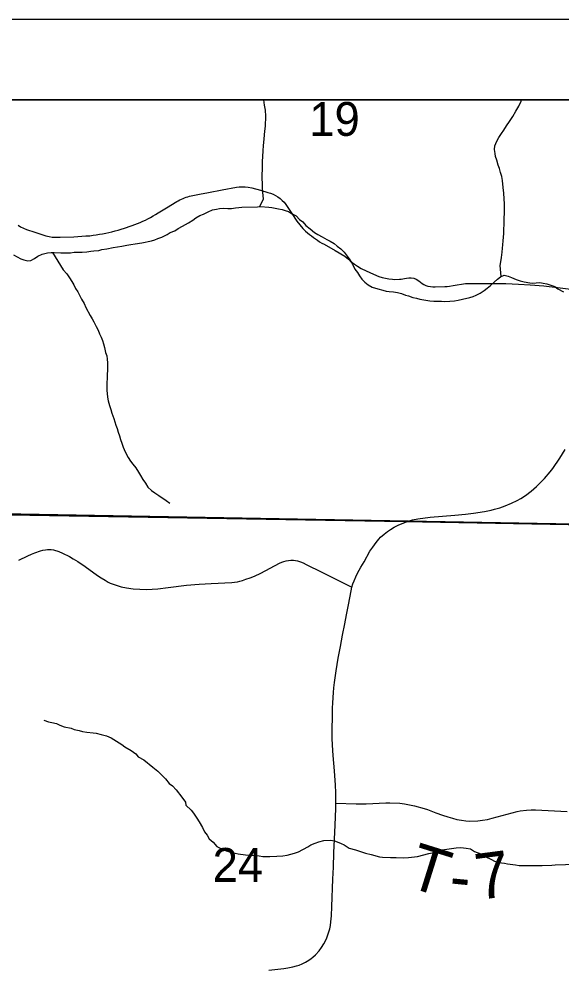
# Model space of a CAD drawing. Extents: x 0 to 34, y 0 to 22.
# Drawn here: x 29.074 to 29.746, y 19.826 to 21 of the extents above; entities that cross this region are included whole.
import ezdxf

# ---------------------------------------------------------------- set-up
doc = ezdxf.new("R2010")
doc.units = 0
for name, color, linetype in [('GM_X_Corporation', 7, 'Continuous'), ('GM_X_County_Road', 7, 'Continuous'), ('GM_X_Minor_River', 7, 'Continuous'), ('GM_X_Section_Text', 7, 'Continuous'), ('GM_X_Township_Road', 7, 'Continuous'), ('GM_X_Township_Road_Text', 7, 'Continuous'), ('SH_Data', 7, 'Continuous')]:
    doc.layers.add(name, color=color, linetype=linetype)

msp = doc.modelspace()

# ---------------------------------------------------------------- linework, layer by layer
at = {"layer": 'GM_X_Corporation'}
for points in [[(30.3167, 20.3649), (30.3167, 20.9), (27.1022, 20.9), (27.0898, 20.417), (27.1239, 20.4163), (27.2336, 20.4152), (27.5829, 20.4116), (27.6751, 20.4106), (29.5503, 20.3788)], [(29.9786, 20.9), (28.9521, 20.9), (28.9396, 20.3907), (29.9657, 20.3723)], [(29.9657, 20.3723), (29.946, 19.5413), (28.9198, 19.5578), (28.9396, 20.3907)]]:
    msp.add_lwpolyline(points, close=True, dxfattribs=at)
for points in [[(27.8031, 14.5091), (28.4032, 14.497), (28.7853, 14.4893), (29.1713, 14.4832), (29.2367, 14.4822), (30.3098, 14.464), (30.3167, 14.4639), (30.3167, 20.9), (27.1022, 20.9)], [(27.8031, 14.5091), (28.4032, 14.497), (28.7853, 14.4893), (29.1713, 14.4832), (29.2367, 14.4822), (30.3098, 14.464), (30.3167, 14.4639), (30.3167, 20.3649), (29.5503, 20.3788), (27.6751, 20.4106)]]:
    msp.add_lwpolyline(points, dxfattribs=at)
at = {"layer": 'GM_X_County_Road'}
for points in [[(29.5828, 20.3842), (29.6129, 20.3866), (29.6261, 20.3879), (29.6362, 20.3891), (29.6497, 20.3912), (29.6581, 20.3928), (29.6623, 20.3939), (29.6689, 20.3958), (29.6753, 20.3981), (29.683, 20.4013), (29.69, 20.4047), (29.6945, 20.4073), (29.7006, 20.4111), (29.7074, 20.4161), (29.7142, 20.422), (29.7206, 20.4285), (29.7239, 20.432), (29.7311, 20.4403), (29.7343, 20.4445), (29.7427, 20.457), (29.7494, 20.4679)], [(29.3833, 19.8242), (29.4016, 19.8262), (29.4065, 19.8269), (29.4127, 19.8282), (29.4172, 19.8293), (29.4208, 19.8304), (29.4243, 19.8318), (29.4286, 19.8339), (29.4326, 19.8363), (29.4356, 19.8385), (29.4374, 19.84), (29.4407, 19.843), (29.4452, 19.8479), (29.4482, 19.852), (29.4512, 19.8567), (29.4546, 19.863), (29.4566, 19.869), (29.4585, 19.8753), (29.4594, 19.8794), (29.46, 19.8837), (29.4605, 19.8912), (29.4612, 19.903), (29.4624, 19.9364), (29.463, 19.9514), (29.4637, 19.9692), (29.4644, 19.986), (29.4651, 20.0034), (29.466, 20.0238), (29.466, 20.0304), (29.4659, 20.0439), (29.4655, 20.0529), (29.4643, 20.0707), (29.4626, 20.0894), (29.4618, 20.1024), (29.4614, 20.1109), (29.4613, 20.1202), (29.4617, 20.139), (29.4619, 20.1482), (29.4623, 20.1547), (29.4631, 20.1674), (29.4636, 20.1733), (29.4644, 20.1796), (29.4665, 20.1943), (29.469, 20.2098), (29.4716, 20.2241), (29.4743, 20.2381), (29.4771, 20.2522), (29.4793, 20.2632), (29.4813, 20.2737), (29.4837, 20.2863), (29.4858, 20.2975), (29.4872, 20.3017), (29.4885, 20.3054), (29.4907, 20.3103), (29.4929, 20.3147), (29.4971, 20.3222), (29.501, 20.3291), (29.5081, 20.3419), (29.5116, 20.3469), (29.5159, 20.3527), (29.5192, 20.357), (29.5214, 20.3593), (29.5256, 20.3633), (29.5299, 20.3665), (29.5337, 20.369), (29.5383, 20.3717), (29.5438, 20.3745), (29.5492, 20.3769), (29.5541, 20.3787), (29.5609, 20.3808), (29.5674, 20.3821), (29.5828, 20.3842)]]:
    msp.add_lwpolyline(points, dxfattribs=at)
at = {"layer": 'GM_X_Minor_River'}
for points in [[(29.3716, 20.7679), (29.3767, 20.7772), (29.3758, 20.7859), (29.3753, 20.7908), (29.375, 20.8087), (29.3753, 20.8132), (29.3755, 20.8234), (29.376, 20.8371), (29.3766, 20.8436), (29.3773, 20.8515), (29.3779, 20.8569), (29.3782, 20.8614), (29.3789, 20.8675), (29.3794, 20.88), (29.3789, 20.8872), (29.378, 20.8933), (29.3772, 20.9)], [(29.6705, 20.6816), (29.6691, 20.6952), (29.6698, 20.6998), (29.6708, 20.7051), (29.6714, 20.7116), (29.6721, 20.7165), (29.6724, 20.7207), (29.6727, 20.7256), (29.6734, 20.7302), (29.6737, 20.7348), (29.6736, 20.7401), (29.6739, 20.7461), (29.6742, 20.7503), (29.6741, 20.7545), (29.6744, 20.759), (29.6743, 20.7628), (29.6746, 20.7712), (29.6736, 20.7848), (29.6727, 20.7916), (29.6718, 20.8003), (29.671, 20.8052), (29.6697, 20.8102), (29.6681, 20.8151), (29.6665, 20.8192), (29.6649, 20.8256), (29.6633, 20.8301), (29.6629, 20.8339), (29.662, 20.8388), (29.6627, 20.8434), (29.6649, 20.8491), (29.6675, 20.8533), (29.6708, 20.8583), (29.6737, 20.8626), (29.677, 20.8679), (29.6807, 20.8733), (29.6848, 20.8794), (29.6885, 20.886), (29.6921, 20.8921), (29.6951, 20.8986), (29.6954, 20.9)], [(29.0676, 20.7084), (29.0767, 20.7036), (29.0805, 20.7021), (29.0855, 20.7011), (29.0892, 20.7015), (29.0937, 20.7039), (29.0975, 20.707), (29.1031, 20.7094), (29.1095, 20.711), (29.114, 20.7115), (29.1178, 20.7115), (29.1262, 20.7109), (29.1379, 20.7111), (29.1424, 20.7116), (29.1523, 20.7118), (29.1583, 20.7123), (29.1632, 20.7131), (29.167, 20.7132), (29.173, 20.714), (29.1768, 20.7149), (29.1828, 20.7157), (29.1908, 20.7174), (29.196, 20.7182), (29.2013, 20.7191), (29.2077, 20.7203), (29.2126, 20.7212), (29.2179, 20.722), (29.2262, 20.7233), (29.2304, 20.7242), (29.2342, 20.725), (29.2383, 20.7258), (29.2421, 20.727), (29.2458, 20.7286), (29.2511, 20.7302), (29.2575, 20.7334), (29.2612, 20.7361), (29.2668, 20.7381), (29.271, 20.7408), (29.2766, 20.7439), (29.2841, 20.7482), (29.2893, 20.7514), (29.2931, 20.7541), (29.2979, 20.7572), (29.3024, 20.7588), (29.3084, 20.7616), (29.3137, 20.7639), (29.3186, 20.7648), (29.3224, 20.7656), (29.3269, 20.7661), (29.3326, 20.7658), (29.3371, 20.7659), (29.342, 20.7664)], [(29.342, 20.7664), (29.3462, 20.7668), (29.35, 20.7673), (29.3693, 20.7676), (29.373, 20.768), (29.3833, 20.7675), (29.3871, 20.7668), (29.3912, 20.7661), (29.395, 20.7654), (29.3996, 20.7643), (29.4034, 20.7633), (29.4076, 20.7622), (29.4114, 20.7596), (29.4168, 20.7567), (29.421, 20.7522), (29.4252, 20.7493), (29.4291, 20.7448), (29.4341, 20.7407), (29.4398, 20.7359), (29.4436, 20.7337), (29.449, 20.7307), (29.4547, 20.7274), (29.4589, 20.7252), (29.4639, 20.7223), (29.4677, 20.7193), (29.4723, 20.716), (29.4762, 20.7119), (29.4801, 20.707), (29.4832, 20.7021), (29.4867, 20.6969), (29.4894, 20.6909), (29.4929, 20.6868), (29.4952, 20.6823), (29.498, 20.6785), (29.5018, 20.6748), (29.506, 20.6714), (29.511, 20.6685), (29.5178, 20.6664), (29.5239, 20.6649), (29.5281, 20.6635), (29.5319, 20.6632), (29.5372, 20.6625), (29.5421, 20.6619), (29.5471, 20.6608), (29.552, 20.6586), (29.5558, 20.6576), (29.5612, 20.6558), (29.5657, 20.6547), (29.5699, 20.6536), (29.5771, 20.6522), (29.5821, 20.6516), (29.587, 20.6513), (29.5911, 20.651), (29.5968, 20.6511), (29.6006, 20.6508), (29.607, 20.6513), (29.6127, 20.6517), (29.6172, 20.6526), (29.6225, 20.6538), (29.6316, 20.6555), (29.6357, 20.6571), (29.6394, 20.6587), (29.6443, 20.661), (29.6492, 20.6642), (29.6529, 20.6673), (29.657, 20.6704), (29.6615, 20.6746), (29.666, 20.6785), (29.6697, 20.6812), (29.6742, 20.6832), (29.6788, 20.6821), (29.683, 20.6803), (29.6887, 20.6781), (29.694, 20.6763), (29.6986, 20.6749), (29.7058, 20.6739), (29.7096, 20.6736), (29.7137, 20.6737), (29.7183, 20.6741), (29.7224, 20.6734), (29.727, 20.6724), (29.7365, 20.6691), (29.7403, 20.6666), (29.7476, 20.6629)], [(29.1156, 20.7115), (29.1288, 20.6897), (29.1334, 20.6849), (29.1369, 20.68), (29.1397, 20.6755), (29.142, 20.6714), (29.1443, 20.6669), (29.1471, 20.6628), (29.1518, 20.6537), (29.1549, 20.6481), (29.1572, 20.6432), (29.1623, 20.6334), (29.1647, 20.6293), (29.167, 20.6256), (29.1698, 20.6199), (29.1721, 20.6154), (29.1741, 20.6109), (29.176, 20.6068), (29.1776, 20.6026), (29.1788, 20.5985), (29.1801, 20.5939), (29.1813, 20.5879), (29.1829, 20.5834), (29.1833, 20.5796), (29.1838, 20.5751), (29.1839, 20.5671), (29.1833, 20.5591), (29.1834, 20.5553), (29.1831, 20.5511), (29.1828, 20.5455), (29.1829, 20.5413), (29.1838, 20.5326), (29.1846, 20.528), (29.1862, 20.522), (29.1878, 20.5171), (29.189, 20.5126), (29.1918, 20.5062), (29.1942, 20.4979), (29.1958, 20.4937), (29.197, 20.4892), (29.1986, 20.4847), (29.1998, 20.4801), (29.2014, 20.4756), (29.203, 20.4707), (29.2058, 20.4647), (29.2093, 20.4579), (29.2124, 20.4534), (29.2151, 20.4497), (29.219, 20.4452), (29.2221, 20.4396), (29.2244, 20.4355), (29.2276, 20.4306), (29.2307, 20.4261), (29.2338, 20.4212), (29.238, 20.4171), (29.2422, 20.4142), (29.2472, 20.4108), (29.2564, 20.4049), (29.261, 20.4016)], [(29.1052, 20.1333), (29.111, 20.1311), (29.1148, 20.1301), (29.1208, 20.129), (29.125, 20.1268), (29.1304, 20.125), (29.1387, 20.1233), (29.1425, 20.1215), (29.1486, 20.1204), (29.1528, 20.119), (29.1581, 20.1183), (29.1661, 20.1177), (29.1699, 20.117), (29.1759, 20.1156), (29.1824, 20.1138), (29.1885, 20.1113), (29.2015, 20.1032), (29.2053, 20.1002), (29.213, 20.0958), (29.2187, 20.0917), (29.2218, 20.088), (29.2287, 20.0843), (29.2398, 20.075), (29.246, 20.0702), (29.2495, 20.0665), (29.2556, 20.0605), (29.2599, 20.0549), (29.2641, 20.0519), (29.2687, 20.0471), (29.2757, 20.0381), (29.28, 20.0317), (29.2808, 20.0279), (29.2873, 20.022), (29.29, 20.0182), (29.2943, 20.0119), (29.297, 20.0074), (29.3013, 20.0006), (29.3037, 19.9953), (29.3068, 19.9912), (29.3095, 19.9863), (29.3145, 19.9823), (29.3188, 19.977), (29.3245, 19.9741), (29.3306, 19.9716), (29.3378, 19.9694), (29.3454, 19.968), (29.3545, 19.9667), (29.3606, 19.9664), (29.3647, 19.9657), (29.3712, 19.9654), (29.3757, 19.9648), (29.3799, 19.9645), (29.3844, 19.9645), (29.3931, 19.9651), (29.4003, 19.9656), (29.406, 19.9664), (29.4105, 19.9677), (29.415, 19.9689), (29.4199, 19.9705), (29.4312, 19.9764), (29.4353, 19.9791), (29.4405, 19.9811), (29.445, 19.9827), (29.4511, 19.9843), (29.4598, 19.9849), (29.4655, 19.9834), (29.4727, 19.9805), (29.4765, 19.9791), (29.4823, 19.975), (29.4903, 19.9729), (29.4963, 19.9707), (29.5028, 19.9689), (29.5096, 19.9672), (29.5199, 19.9643), (29.5237, 19.964), (29.5336, 19.9634), (29.5404, 19.9632), (29.5502, 19.9629), (29.5559, 19.9634), (29.5668, 19.9648), (29.5811, 19.9684), (29.5872, 19.9697), (29.5909, 19.9709), (29.5951, 19.9725), (29.603, 19.9738), (29.609, 19.9746), (29.6147, 19.9755), (29.6204, 19.9756), (29.6272, 19.9749), (29.6325, 19.9739), (29.6375, 19.971), (29.6451, 19.9681), (29.6512, 19.9644), (29.6585, 19.9611), (29.6623, 19.9589), (29.6672, 19.9574), (29.6744, 19.9564), (29.6782, 19.9554), (29.6881, 19.9544), (29.6927, 19.9537), (29.7021, 19.9535)], [(29.7021, 19.9535), (29.7089, 19.9533), (29.721, 19.9535), (29.7328, 19.9541), (29.7369, 19.9545), (29.7626, 19.955)]]:
    msp.add_lwpolyline(points, dxfattribs=at)
at = {"layer": 'GM_X_Township_Road'}
for points in [[(29.0733, 20.7452), (29.0764, 20.7432), (29.0798, 20.7414), (29.0838, 20.7399), (29.0939, 20.7365), (29.1038, 20.733), (29.1076, 20.7319), (29.1115, 20.731), (29.1154, 20.7304), (29.1194, 20.7301), (29.1253, 20.7303), (29.142, 20.7309), (29.157, 20.7318), (29.1621, 20.7321), (29.166, 20.7326), (29.1699, 20.7331), (29.1738, 20.7338), (29.1777, 20.7345), (29.1816, 20.7352), (29.1855, 20.7361), (29.1893, 20.737), (29.1932, 20.738), (29.197, 20.7391), (29.2008, 20.7402), (29.2046, 20.7414), (29.2073, 20.7423), (29.2107, 20.7434), (29.2141, 20.7446), (29.2174, 20.7458), (29.2208, 20.7471), (29.2241, 20.7485), (29.2274, 20.75), (29.2306, 20.7515), (29.2338, 20.7531), (29.237, 20.7548), (29.2401, 20.7566), (29.2432, 20.7584), (29.2463, 20.7602), (29.2566, 20.7664), (29.2695, 20.7744), (29.2713, 20.7754), (29.2732, 20.7764), (29.2751, 20.7773), (29.2771, 20.7782), (29.279, 20.779), (29.281, 20.7797), (29.2831, 20.7803), (29.2851, 20.7809), (29.2872, 20.7814), (29.2892, 20.7818), (29.2975, 20.7834), (29.3088, 20.7856), (29.3255, 20.7887), (29.3431, 20.7919), (29.3465, 20.7924), (29.3495, 20.7926), (29.3541, 20.7924), (29.3577, 20.7921), (29.3622, 20.7911), (29.3727, 20.7883), (29.382, 20.7857), (29.3852, 20.7845), (29.3884, 20.7834), (29.3916, 20.782), (29.3945, 20.7801), (29.397, 20.778), (29.3996, 20.7758), (29.402, 20.7734), (29.4042, 20.7708), (29.4117, 20.7595), (29.4178, 20.7502), (29.4251, 20.741), (29.4286, 20.7378), (29.431, 20.7357), (29.4334, 20.7337), (29.4358, 20.7318), (29.4383, 20.7299), (29.4408, 20.7281), (29.4434, 20.7264), (29.446, 20.7247), (29.4487, 20.723), (29.4514, 20.7215), (29.4652, 20.7137), (29.4771, 20.7066), (29.4794, 20.7048), (29.4817, 20.7029), (29.4839, 20.701), (29.4862, 20.699), (29.489, 20.6968), (29.4926, 20.6944), (29.4973, 20.6916), (29.5034, 20.6885), (29.5127, 20.6844), (29.5193, 20.6817), (29.5234, 20.6804), (29.5275, 20.6794), (29.5317, 20.6786), (29.5359, 20.6782), (29.5381, 20.6781), (29.5445, 20.6783), (29.5466, 20.6785), (29.5487, 20.6788), (29.5508, 20.6792), (29.5534, 20.6796), (29.5564, 20.68), (29.5592, 20.6799), (29.5625, 20.6794), (29.5653, 20.6783), (29.5685, 20.6762), (29.5705, 20.6747), (29.5726, 20.6731), (29.5749, 20.6717), (29.5773, 20.6706), (29.5798, 20.6698), (29.583, 20.6693), (29.586, 20.669), (29.5889, 20.6689), (29.6007, 20.6691), (29.6037, 20.6693), (29.6066, 20.6696), (29.6111, 20.6704), (29.6161, 20.6714), (29.6212, 20.6723), (29.6263, 20.6729), (29.6315, 20.6732), (29.6387, 20.6731), (29.6551, 20.673), (29.6761, 20.6729), (29.6918, 20.6723), (29.7061, 20.6714), (29.7232, 20.67), (29.7433, 20.6675), (29.7597, 20.6656)], [(29.0741, 20.3308), (29.0854, 20.3364), (29.0898, 20.3384), (29.0941, 20.3402), (29.1009, 20.3425), (29.104, 20.3433), (29.1073, 20.3438), (29.1096, 20.3441), (29.1118, 20.3441), (29.114, 20.3441), (29.117, 20.3437), (29.1196, 20.3431), (29.1213, 20.3426), (29.1237, 20.3417), (29.1283, 20.3398), (29.137, 20.3355), (29.1415, 20.3328), (29.147, 20.3294), (29.156, 20.3231), (29.1715, 20.3122), (29.1759, 20.3091), (29.1807, 20.3061), (29.1845, 20.3039), (29.187, 20.3027), (29.1897, 20.3017), (29.1934, 20.3004), (29.1984, 20.2988), (29.2007, 20.2982), (29.2074, 20.2968), (29.2157, 20.2957), (29.2237, 20.295), (29.232, 20.2949), (29.2461, 20.2957), (29.2587, 20.2972), (29.2815, 20.2999), (29.2969, 20.3012), (29.3121, 20.3022), (29.3374, 20.3034), (29.3409, 20.3037), (29.3445, 20.3043), (29.3474, 20.3049), (29.3507, 20.3059), (29.3549, 20.3073), (29.3602, 20.3091), (29.3655, 20.3113), (29.3731, 20.315), (29.3964, 20.3273), (29.3991, 20.3285), (29.4019, 20.3295), (29.4048, 20.3303), (29.4077, 20.3307), (29.4105, 20.3309), (29.4137, 20.3308), (29.4185, 20.33), (29.4222, 20.3289), (29.4258, 20.3275), (29.4295, 20.3258), (29.4487, 20.3162), (29.4653, 20.3078), (29.4858, 20.2975)], [(29.466, 20.0304), (29.4913, 20.0298), (29.5035, 20.0297), (29.5278, 20.0309), (29.5326, 20.031), (29.5449, 20.0305), (29.551, 20.0298), (29.557, 20.0287), (29.5633, 20.0273), (29.5751, 20.0241), (29.5792, 20.0228), (29.5898, 20.0188), (29.598, 20.0158), (29.6046, 20.0135), (29.6101, 20.0119), (29.6157, 20.0105), (29.6215, 20.0094), (29.6266, 20.0088), (29.6317, 20.0085), (29.6415, 20.0088), (29.6474, 20.0095), (29.6534, 20.0105), (29.6592, 20.0119), (29.6901, 20.0203), (29.6938, 20.0211), (29.7017, 20.022), (29.7073, 20.0222), (29.7128, 20.0222), (29.7518, 20.0201)]]:
    msp.add_lwpolyline(points, dxfattribs=at)
at = {"layer": 'SH_Data'}
for points in [[(23.4167, 21), (30.4167, 21), (30.4167, 14), (23.4167, 14)], [(23.5167, 20.9), (30.3167, 20.9), (30.3167, 14.1), (23.5167, 14.1)]]:
    msp.add_lwpolyline(points, close=True, dxfattribs=at)

# ---------------------------------------------------------------- texts
at = {"layer": 'GM_X_Section_Text'}
for s, p in [('19', (29.4333, 20.8555)), ('24', (29.3137, 19.9333))]:
    msp.add_text(s, height=0.04186, rotation=0, dxfattribs=at).set_placement(p)
at = {"layer": 'GM_X_Township_Road_Text'}
for s, rotation, p in [('T', 342.591, (29.552, 19.928)), ('7', 7.4896, (29.642, 19.9108)), ('-', 354.4397, (29.6049, 19.9128))]:
    msp.add_text(s, height=0.0568, rotation=rotation, dxfattribs=at).set_placement(p)

doc.saveas('drawing.dxf')
